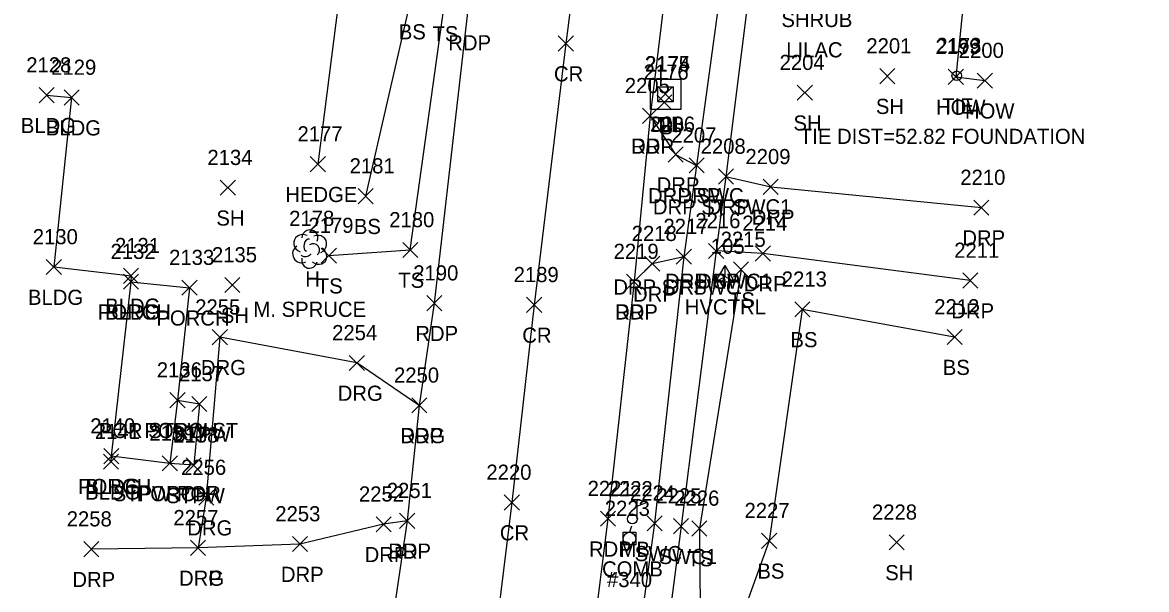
# Model space of a CAD drawing. Extents: x 1651305 to 1654558, y 539481 to 548441.
# Drawn here: x 1654294.9 to 1654443.3, y 544140.4 to 544215.2 of the extents above; entities that cross this region are included whole.
import ezdxf

# ---------------------------------------------------------------- set-up
doc = ezdxf.new("R2010")
doc.units = 0
for name, color, linetype in [('C_A', 7, 'Continuous'), ('C_C', 7, 'Continuous'), ('C_I', 7, 'Continuous'), ('CBP', 7, 'Continuous'), ('CPSM', 7, 'Continuous'), ('D_A', 7, 'Continuous'), ('D_I', 7, 'Continuous'), ('D_TIC', 7, 'Continuous'), ('DS', 7, 'Continuous'), ('L_A', 7, 'Continuous'), ('L_C', 7, 'Continuous'), ('L_I', 7, 'Continuous'), ('L_TIC', 7, 'Continuous'), ('LAHR', 7, 'Continuous'), ('LBC', 7, 'Continuous'), ('LBF', 7, 'Continuous'), ('LELB', 7, 'Continuous'), ('LMB', 7, 'Continuous'), ('LTD', 7, 'Continuous'), ('P_A', 7, 'Continuous'), ('P_I', 7, 'Continuous'), ('P_TIC', 7, 'Continuous'), ('PET', 7, 'Continuous'), ('PRC', 7, 'Continuous'), ('R_A', 7, 'Continuous'), ('R_I', 7, 'Continuous'), ('R_TIC', 7, 'Continuous'), ('RDG', 7, 'Continuous'), ('RDP', 7, 'Continuous'), ('RSW', 7, 'Continuous'), ('U_A', 7, 'Continuous'), ('U_I', 7, 'Continuous'), ('UP', 7, 'Continuous')]:
    doc.layers.add(name, color=color, linetype=linetype)

msp = doc.modelspace()

# ---------------------------------------------------------------- linework, layer by layer
at = {"layer": 'CBP'}
for radius in [0.625, 0.0833]:
    msp.add_circle((1654418.22, 544208.21), radius, dxfattribs=at)
at = {"layer": 'CPSM'}
for p, q in [((1654386.39, 544180.99), (1654387.64, 544183.16)), ((1654388.89, 544180.99), (1654387.64, 544183.16)), ((1654387.64, 544181.71), (1654387.64, 544183.16)), ((1654386.39, 544180.99), (1654387.64, 544181.71)), ((1654386.39, 544180.99), (1654388.89, 544180.99)), ((1654387.64, 544181.71), (1654387.64, 544181.71)), ((1654387.64, 544181.71), (1654388.89, 544180.99))]:
    msp.add_line(p, q, dxfattribs=at)
at = {"layer": 'D_TIC'}
for points in [[(1654378.75, 544204.8), (1654380.75, 544206.8)], [(1654380.75, 544204.8), (1654378.75, 544206.8)], [(1654378.63, 544203.69), (1654380.63, 544205.69)], [(1654380.63, 544203.69), (1654378.63, 544205.69)]]:
    msp.add_lwpolyline(points, dxfattribs=at)
at = {"layer": 'DS'}
for p, q in [((1654377.79, 544207.76), (1654381.79, 544207.76)), ((1654377.79, 544203.76), (1654377.79, 544207.76)), ((1654381.79, 544207.76), (1654381.79, 544203.76)), ((1654378.79, 544204.76), (1654378.79, 544206.76)), ((1654378.79, 544206.76), (1654380.79, 544206.76)), ((1654380.79, 544206.76), (1654380.79, 544204.76)), ((1654380.79, 544204.76), (1654378.79, 544204.76)), ((1654379.79, 544205.76), (1654379.79, 544205.76)), ((1654379.79, 544205.76), (1654379.79, 544205.76)), ((1654381.79, 544203.76), (1654377.79, 544203.76))]:
    msp.add_line(p, q, dxfattribs=at)
at = {"layer": 'L_TIC'}
for points in [[(1654408.06, 544207.16), (1654410.06, 544209.16)], [(1654410.06, 544207.16), (1654408.06, 544209.16)], [(1654417.1, 544207.06), (1654419.1, 544209.06)], [(1654419.1, 544207.06), (1654417.1, 544209.06)], [(1654420.92, 544206.56), (1654422.92, 544208.56)], [(1654422.92, 544206.56), (1654420.92, 544208.56)], [(1654297.1, 544204.64), (1654299.1, 544206.64)], [(1654299.1, 544204.64), (1654297.1, 544206.64)], [(1654300.4, 544204.33), (1654302.4, 544206.33)], [(1654302.4, 544204.33), (1654300.4, 544206.33)], [(1654397.18, 544204.97), (1654399.18, 544206.97)], [(1654399.18, 544204.97), (1654397.18, 544206.97)], [(1654332.9, 544195.54), (1654334.9, 544197.54)], [(1654334.9, 544195.54), (1654332.9, 544197.54)], [(1654321.01, 544192.43), (1654323.01, 544194.43)], [(1654323.01, 544192.43), (1654321.01, 544194.43)], [(1654339.21, 544191.32), (1654341.21, 544193.32)], [(1654341.21, 544191.32), (1654339.21, 544193.32)], [(1654334.35, 544183.47), (1654336.35, 544185.47)], [(1654336.35, 544183.47), (1654334.35, 544185.47)], [(1654345.1, 544184.22), (1654347.1, 544186.22)], [(1654347.1, 544184.22), (1654345.1, 544186.22)], [(1654298.05, 544181.97), (1654300.05, 544183.97)], [(1654300.05, 544181.97), (1654298.05, 544183.97)], [(1654308.24, 544180.8), (1654310.24, 544182.8)], [(1654310.24, 544180.8), (1654308.24, 544182.8)], [(1654388.75, 544181.63), (1654390.75, 544183.63)], [(1654390.75, 544181.63), (1654388.75, 544183.63)], [(1654308.23, 544180.03), (1654310.23, 544182.03)], [(1654310.23, 544180.03), (1654308.23, 544182.03)], [(1654308.23, 544180.03), (1654310.23, 544182.03)], [(1654310.23, 544180.03), (1654308.23, 544182.03)], [(1654315.96, 544179.24), (1654317.96, 544181.24)], [(1654317.96, 544179.24), (1654315.96, 544181.24)], [(1654321.61, 544179.59), (1654323.61, 544181.59)], [(1654323.61, 544179.59), (1654321.61, 544181.59)], [(1654396.83, 544176.38), (1654398.83, 544178.38)], [(1654398.83, 544176.38), (1654396.83, 544178.38)], [(1654416.94, 544172.72), (1654418.94, 544174.72)], [(1654418.94, 544172.72), (1654416.94, 544174.72)], [(1654314.38, 544164.39), (1654316.38, 544166.39)], [(1654316.38, 544164.39), (1654314.38, 544166.39)], [(1654314.38, 544164.39), (1654316.38, 544166.39)], [(1654316.38, 544164.39), (1654314.38, 544166.39)], [(1654317.26, 544163.9), (1654319.26, 544165.9)], [(1654319.26, 544163.9), (1654317.26, 544165.9)], [(1654305.63, 544157), (1654307.63, 544159)], [(1654307.63, 544157), (1654305.63, 544159)], [(1654305.63, 544157), (1654307.63, 544159)], [(1654307.63, 544157), (1654305.63, 544159)], [(1654305.59, 544156.27), (1654307.59, 544158.27)], [(1654307.59, 544156.27), (1654305.59, 544158.27)], [(1654313.37, 544156.06), (1654315.37, 544158.06)], [(1654315.37, 544156.06), (1654313.37, 544158.06)], [(1654313.37, 544156.06), (1654315.37, 544158.06)], [(1654315.37, 544156.06), (1654313.37, 544158.06)], [(1654316.51, 544155.8), (1654318.51, 544157.8)], [(1654318.51, 544155.8), (1654316.51, 544157.8)], [(1654383.25, 544147.47), (1654385.25, 544149.47)], [(1654385.25, 544147.47), (1654383.25, 544149.47)], [(1654392.47, 544145.84), (1654394.47, 544147.84)], [(1654394.47, 544145.84), (1654392.47, 544147.84)], [(1654409.29, 544145.63), (1654411.29, 544147.63)], [(1654411.29, 544145.63), (1654409.29, 544147.63)]]:
    msp.add_lwpolyline(points, dxfattribs=at)
at = {"layer": 'LAHR'}
msp.add_lwpolyline([(1654343.12, 544269.12), (1654333.9, 544196.54)], dxfattribs=at)
at = {"layer": 'LBC'}
for points in [[(1654425.69, 544242.58), (1654421.57, 544242.91), (1654420.13, 544229.87), (1654419.58, 544222.88), (1654418.1, 544208.06), (1654421.92, 544207.56)], [(1654298.1, 544205.64), (1654301.4, 544205.33), (1654299.05, 544182.97), (1654309.24, 544181.8), (1654309.23, 544181.03), (1654306.63, 544158), (1654306.59, 544157.27)]]:
    msp.add_lwpolyline(points, dxfattribs=at)
at = {"layer": 'LBF'}
for points in [[(1654309.23, 544181.03), (1654316.96, 544180.24), (1654315.38, 544165.39), (1654314.37, 544157.06), (1654306.63, 544158)], [(1654315.38, 544165.39), (1654318.26, 544164.9), (1654317.51, 544156.8), (1654314.37, 544157.06)]]:
    msp.add_lwpolyline(points, dxfattribs=at)
at = {"layer": 'LELB'}
for points in [[(1654340.21, 544192.32), (1654346.14, 544218.01), (1654348.85, 544254.55)], [(1654335.35, 544184.47), (1654346.1, 544185.22), (1654350.62, 544217.75), (1654352.84, 544250.3)], [(1654389.75, 544182.63), (1654384.25, 544148.47), (1654384.51, 544121.92), (1654406.01, 544119.98)], [(1654417.94, 544173.72), (1654397.83, 544177.38), (1654393.47, 544146.84), (1654384.51, 544121.92), (1654381.65, 544104.55), (1654379.35, 544091.34), (1654377.04, 544088.64), (1654375.52, 544071.52)]]:
    msp.add_lwpolyline(points, dxfattribs=at)
at = {"layer": 'LMB'}
for p, q in [((1654376.06, 544152.32), (1654377.35, 544151.94)), ((1654376.06, 544149.73), (1654376.06, 544152.32)), ((1654376.06, 544151.42), (1654377.34, 544151.93)), ((1654375.41, 544149.72), (1654375.41, 544149.72))]:
    msp.add_line(p, q, dxfattribs=at)
msp.add_circle((1654375.41, 544149.72), 0.656, dxfattribs=at)
at = {"layer": 'LTD'}
msp.add_line((1654332.8, 544185.39), (1654332.8, 544185.39), dxfattribs=at)
msp.add_line((1654332.8, 544185.39), (1654332.8, 544185.39), dxfattribs=at)
msp.add_arc((1654332.85, 544186.82), 1.05, 335.5272, 180.9563, dxfattribs=at)
for centre, major_axis, ratio, start_param, end_param in [((1654332.01, 544186.05), (1.21, -0.51), 0.895232, 1.570796, 4.712389), ((1654333.84, 544185.97), (-1.14, -0.48), 0.949671, 1.570796, 4.712389), ((1654331.72, 544184.68), (0.58, -1.04), 0.959034, 3.141593, 6.283185), ((1654332.59, 544185.85), (-0.208, -0.792), 0.645439, 3.141593, 6.283185), ((1654333.3, 544185.22), (-0.5, 0.667), 0.989748, 3.141593, 6.283185), ((1654333.8, 544184.55), (-1.09, 0.79), 0.841452, 1.570796, 4.712389), ((1654332.8, 544183.89), (0.26, 1.06), 0.942809, 1.570796, 4.712389), ((1654332.34, 544184.64), (-0.625, -0.083), 0.423636, 0, 3.141593)]:
    msp.add_ellipse(centre, major_axis=major_axis, ratio=ratio, start_param=start_param, end_param=end_param, dxfattribs=at)
at = {"layer": 'P_TIC'}
for points in [[(1654365.63, 544211.46), (1654367.63, 544213.46)], [(1654367.63, 544211.46), (1654365.63, 544213.46)], [(1654376.75, 544201.91), (1654378.75, 544203.91)], [(1654378.75, 544201.91), (1654376.75, 544203.91)], [(1654374.63, 544180.04), (1654376.63, 544182.04)], [(1654376.63, 544180.04), (1654374.63, 544182.04)], [(1654348.27, 544177.19), (1654350.27, 544179.19)], [(1654350.27, 544177.19), (1654348.27, 544179.19)], [(1654361.44, 544176.97), (1654363.44, 544178.97)], [(1654363.44, 544176.97), (1654361.44, 544178.97)], [(1654346.29, 544163.71), (1654348.29, 544165.71)], [(1654348.29, 544163.71), (1654346.29, 544165.71)], [(1654358.49, 544150.89), (1654360.49, 544152.89)], [(1654360.49, 544150.89), (1654358.49, 544152.89)], [(1654344.69, 544148.48), (1654346.69, 544150.48)], [(1654346.69, 544148.48), (1654344.69, 544150.48)], [(1654371.19, 544148.75), (1654373.19, 544150.75)], [(1654373.19, 544148.75), (1654371.19, 544150.75)]]:
    msp.add_lwpolyline(points, dxfattribs=at)
at = {"layer": 'PET'}
for points in [[(1654345.04, 544588.36), (1654350.59, 544607.19), (1654356.58, 544624.31), (1654366.69, 544597.7), (1654378.7, 544565.63), (1654388.8, 544536.02), (1654394.39, 544506.43), (1654399.12, 544481.01), (1654401.13, 544462.89), (1654401.53, 544436.35), (1654401.83, 544421.31), (1654397.37, 544359.7), (1654394.39, 544336.59), (1654391.4, 544308.96), (1654388.94, 544290.74), (1654386.84, 544274.06), (1654380.97, 544229.45), (1654377.75, 544202.91), (1654375.63, 544181.04), (1654372.19, 544149.75), (1654366.61, 544105.72), (1654362.8, 544072.79)], [(1654345.04, 544588.36), (1654352.84, 544566.03), (1654357.71, 544551.64), (1654360.67, 544540.21), (1654367.97, 544503.91), (1654371.19, 544473.22), (1654373.31, 544432.69), (1654372.37, 544396.63), (1654369.95, 544367.4), (1654366.85, 544341.54), (1654364.49, 544322.02), (1654359.18, 544276.5), (1654356.39, 544249.38), (1654353.63, 544216.56), (1654349.27, 544178.19), (1654347.29, 544164.71), (1654345.69, 544149.48), (1654340.92, 544117.48), (1654336.05, 544077.13)]]:
    msp.add_lwpolyline(points, dxfattribs=at)
at = {"layer": 'PRC'}
msp.add_lwpolyline([(1654350.59, 544607.19), (1654355.93, 544592.7), (1654363.68, 544570.63), (1654372.22, 544542.27), (1654380.24, 544505.39), (1654384.95, 544473.92), (1654386.82, 544433.75), (1654385.71, 544395.52), (1654383.86, 544366), (1654380.92, 544339.65), (1654378, 544311.09), (1654373.89, 544274.84), (1654369.01, 544231.01), (1654366.63, 544212.46), (1654362.44, 544177.97), (1654359.49, 544151.89), (1654354.07, 544107.93), (1654348.42, 544063.01)], dxfattribs=at)
at = {"layer": 'R_TIC'}
for points in [[(1654376.75, 544201.91), (1654378.75, 544203.91)], [(1654378.75, 544201.91), (1654376.75, 544203.91)], [(1654380.12, 544196.82), (1654382.12, 544198.82)], [(1654382.12, 544196.82), (1654380.12, 544198.82)], [(1654382.89, 544195.38), (1654384.89, 544197.38)], [(1654384.89, 544195.38), (1654382.89, 544197.38)], [(1654382.89, 544195.38), (1654384.89, 544197.38)], [(1654384.89, 544195.38), (1654382.89, 544197.38)], [(1654386.76, 544193.91), (1654388.76, 544195.91)], [(1654388.76, 544193.91), (1654386.76, 544195.91)], [(1654386.76, 544193.91), (1654388.76, 544195.91)], [(1654388.76, 544193.91), (1654386.76, 544195.91)], [(1654392.67, 544192.54), (1654394.67, 544194.54)], [(1654394.67, 544192.54), (1654392.67, 544194.54)], [(1654420.47, 544189.81), (1654422.47, 544191.81)], [(1654422.47, 544189.81), (1654420.47, 544191.81)], [(1654385.47, 544184.09), (1654387.47, 544186.09)], [(1654387.47, 544184.09), (1654385.47, 544186.09)], [(1654385.47, 544184.09), (1654387.47, 544186.09)], [(1654387.47, 544184.09), (1654385.47, 544186.09)], [(1654391.62, 544183.76), (1654393.62, 544185.76)], [(1654393.62, 544183.76), (1654391.62, 544185.76)], [(1654377.02, 544182.4), (1654379.02, 544184.4)], [(1654379.02, 544182.4), (1654377.02, 544184.4)], [(1654381.2, 544183.33), (1654383.2, 544185.33)], [(1654383.2, 544183.33), (1654381.2, 544185.33)], [(1654381.2, 544183.33), (1654383.2, 544185.33)], [(1654383.2, 544183.33), (1654381.2, 544185.33)], [(1654374.63, 544180.04), (1654376.63, 544182.04)], [(1654376.63, 544180.04), (1654374.63, 544182.04)], [(1654419.01, 544180.18), (1654421.01, 544182.18)], [(1654421.01, 544180.18), (1654419.01, 544182.18)], [(1654319.97, 544172.7), (1654321.97, 544174.7)], [(1654321.97, 544172.7), (1654319.97, 544174.7)], [(1654338.04, 544169.31), (1654340.04, 544171.31)], [(1654340.04, 544169.31), (1654338.04, 544171.31)], [(1654346.29, 544163.71), (1654348.29, 544165.71)], [(1654348.29, 544163.71), (1654346.29, 544165.71)], [(1654318.17, 544151.54), (1654320.17, 544153.54)], [(1654320.17, 544151.54), (1654318.17, 544153.54)], [(1654341.58, 544148.02), (1654343.58, 544150.02)], [(1654343.58, 544148.02), (1654341.58, 544150.02)], [(1654344.69, 544148.48), (1654346.69, 544150.48)], [(1654346.69, 544148.48), (1654344.69, 544150.48)], [(1654377.35, 544148.15), (1654379.35, 544150.15)], [(1654379.35, 544148.15), (1654377.35, 544150.15)], [(1654380.83, 544147.77), (1654382.83, 544149.77)], [(1654382.83, 544147.77), (1654380.83, 544149.77)], [(1654317.09, 544144.9), (1654319.09, 544146.9)], [(1654319.09, 544144.9), (1654317.09, 544146.9)], [(1654317.09, 544144.9), (1654319.09, 544146.9)], [(1654319.09, 544144.9), (1654317.09, 544146.9)], [(1654330.54, 544145.41), (1654332.54, 544147.41)], [(1654332.54, 544145.41), (1654330.54, 544147.41)], [(1654303.01, 544144.73), (1654305.01, 544146.73)], [(1654305.01, 544144.73), (1654303.01, 544146.73)]]:
    msp.add_lwpolyline(points, dxfattribs=at)
at = {"layer": 'RDG'}
msp.add_lwpolyline([(1654347.29, 544164.71), (1654339.04, 544170.31), (1654320.97, 544173.7), (1654319.17, 544152.54), (1654318.09, 544145.9)], dxfattribs=at)
at = {"layer": 'RDP'}
for points in [[(1654377.75, 544202.91), (1654381.12, 544197.82), (1654383.89, 544196.38)], [(1654387.76, 544194.91), (1654393.67, 544193.54), (1654421.47, 544190.81)], [(1654382.2, 544184.33), (1654378.02, 544183.4), (1654375.63, 544181.04)], [(1654420.01, 544181.18), (1654392.62, 544184.76), (1654386.47, 544185.09)], [(1654345.69, 544149.48), (1654342.58, 544149.02), (1654331.54, 544146.41), (1654318.09, 544145.9), (1654304.01, 544145.73)]]:
    msp.add_lwpolyline(points, dxfattribs=at)
at = {"layer": 'RSW'}
for points in [[(1654407.4, 544661.78), (1654407.29, 544658.87), (1654407.96, 544657.88), (1654443.27, 544654.59), (1654438.81, 544619.89), (1654433.56, 544580.17), (1654430.14, 544553.99), (1654428.03, 544537.28), (1654424.83, 544512.84), (1654419.77, 544473.61), (1654412.66, 544419.66), (1654404.12, 544354.77), (1654402.1, 544339.77), (1654395.49, 544286.06), (1654394.01, 544276.12), (1654388.39, 544229.58), (1654383.89, 544196.38), (1654382.2, 544184.33), (1654378.35, 544149.15), (1654372.36, 544105.49), (1654368.55, 544072.05)], [(1654411.79, 544225.19), (1654397.44, 544226.9), (1654391.8, 544227.25), (1654387.76, 544194.91), (1654386.47, 544185.09), (1654381.83, 544148.77), (1654376.18, 544105.12), (1654374.34, 544091.89), (1654373.97, 544088.88), (1654371.75, 544071.94)]]:
    msp.add_lwpolyline(points, dxfattribs=at)
at = {"layer": 'UP'}
for p, q in [((1654375.28, 544148.79), (1654375.03, 544147.96)), ((1654374.19, 544146.29), (1654374.19, 544147.96)), ((1654374.19, 544147.96), (1654375.86, 544147.96)), ((1654375.03, 544147.13), (1654375.03, 544147.13)), ((1654375.86, 544147.96), (1654375.86, 544146.29)), ((1654375.86, 544146.29), (1654374.19, 544146.29)), ((1654374.78, 544145.46), (1654375.03, 544146.29))]:
    msp.add_line(p, q, dxfattribs=at)
msp.add_circle((1654375.03, 544147.13), 0.833, dxfattribs=at)

# ---------------------------------------------------------------- texts
at = {"layer": 'C_A'}
for s, p in [('TIE', (1654416.3, 544203.21)), ('HVCTRL', (1654382.33, 544176.71))]:
    msp.add_text(s, height=2, dxfattribs=at).set_placement(p)
at = {"layer": 'C_C'}
msp.add_text('TIE DIST=52.82 FOUNDATION', height=2, dxfattribs=at).set_placement((1654397.52, 544199.21))
at = {"layer": 'C_I'}
for s, p in [('2173', (1654415.53, 544211.21)), ('105', (1654385.77, 544184.71))]:
    msp.add_text(s, height=2, dxfattribs=at).set_placement(p)
at = {"layer": 'D_A'}
for s, p in [('DIB', (1654377.85, 544200.8)), ('DI', (1654378.85, 544200.76)), ('P', (1654379.01, 544199.69))]:
    msp.add_text(s, height=2, dxfattribs=at).set_placement(p)
at = {"layer": 'D_I'}
for s, p in [('2175', (1654377.06, 544208.8)), ('2174', (1654377.1, 544208.76)), ('2176', (1654376.89, 544207.69))]:
    msp.add_text(s, height=2, dxfattribs=at).set_placement(p)
at = {"layer": 'L_A'}
for s, p in [('SHRUB', (1654395.08, 544214.63)), ('BS', (1654344.58, 544213.01)), ('TS', (1654349.03, 544212.75)), ('SH', (1654407.55, 544203.16)), ('HOW', (1654415.49, 544203.06)), ('HOW', (1654419.3, 544202.56)), ('BLDG', (1654294.69, 544200.64)), ('BLDG', (1654297.99, 544200.33)), ('SH', (1654396.67, 544200.97)), ('HEDGE', (1654329.6, 544191.54)), ('SH', (1654320.5, 544188.43)), ('BS', (1654338.65, 544187.32)), ('H', (1654332.23, 544180.39)), ('TS', (1654333.76, 544179.47)), ('TS', (1654344.51, 544180.22)), ('BLDG', (1654295.64, 544177.97)), ('TS', (1654388.16, 544177.63)), ('PORCH', (1654304.85, 544176.03)), ('BLDG', (1654305.82, 544176.03)), ('BLDG', (1654305.83, 544176.8)), ('PORCH', (1654312.59, 544175.24)), ('SH', (1654321.1, 544175.59)), ('BS', (1654396.27, 544172.38)), ('BS', (1654416.38, 544168.72)), ('POR STPW ST', (1654304.97, 544160.39)), ('PORCH', (1654311.01, 544160.39)), ('STPW', (1654314.66, 544159.9)), ('PORCH', (1654302.25, 544153)), ('BLDG', (1654303.18, 544152.27)), ('BLDG', (1654303.22, 544153)), ('STPW POR', (1654306.82, 544152.06)), ('PORCH', (1654309.99, 544152.06)), ('STPW', (1654313.9, 544151.8)), ('MB', (1654373.71, 544144.72)), ('TS', (1654382.66, 544143.47)), ('BS', (1654391.91, 544141.84)), ('SH', (1654408.78, 544141.63))]:
    msp.add_text(s, height=2, dxfattribs=at).set_placement(p)
at = {"layer": 'L_C'}
for s, p in [('LILAC', (1654395.72, 544210.63)), ('M. SPRUCE', (1654325.4, 544176.39)), ('#340', (1654372.06, 544140.72))]:
    msp.add_text(s, height=2, dxfattribs=at).set_placement(p)
at = {"layer": 'L_I'}
for s, p in [('2201', (1654406.29, 544211.16)), ('2199', (1654415.4, 544211.06)), ('2200', (1654418.49, 544210.56)), ('2128', (1654295.41, 544208.64)), ('2204', (1654394.84, 544208.97)), ('2129', (1654298.7, 544208.33)), ('2177', (1654331.21, 544199.54)), ('2134', (1654319.32, 544196.43)), ('2181', (1654338.09, 544195.32)), ('2178', (1654330.11, 544188.39)), ('2180', (1654343.32, 544188.22)), ('2179', (1654332.65, 544187.47)), ('2130', (1654296.27, 544185.97)), ('2215', (1654387.06, 544185.63)), ('2132', (1654306.54, 544184.03)), ('2132', (1654306.54, 544184.03)), ('2131', (1654307.12, 544184.8)), ('2135', (1654319.92, 544183.59)), ('2133', (1654314.27, 544183.24)), ('2213', (1654395.13, 544180.38)), ('2212', (1654415.25, 544176.72)), ('2136', (1654312.64, 544168.39)), ('2136', (1654312.64, 544168.39)), ('2137', (1654315.57, 544167.9)), ('2140', (1654303.85, 544161)), ('2140', (1654303.85, 544161)), ('2141', (1654304.46, 544160.27)), ('2139', (1654311.67, 544160.06)), ('2139', (1654311.67, 544160.06)), ('2138', (1654314.81, 544159.8)), ('2222', (1654372.15, 544152.72)), ('2226', (1654380.94, 544151.47)), ('2227', (1654390.21, 544149.84)), ('2228', (1654407.03, 544149.63))]:
    msp.add_text(s, height=2, dxfattribs=at).set_placement(p)
at = {"layer": 'P_A'}
for s, p in [('RDP', (1654351.11, 544211.56)), ('CR', (1654365.06, 544207.46)), ('RDP', (1654375.24, 544197.91)), ('RDP', (1654373.12, 544176.04)), ('RDP', (1654346.76, 544173.19)), ('CR', (1654360.88, 544172.97)), ('RDP', (1654344.78, 544159.71)), ('CR', (1654357.92, 544146.89)), ('RDP', (1654343.18, 544144.48)), ('RDP', (1654369.68, 544144.75))]:
    msp.add_text(s, height=2, dxfattribs=at).set_placement(p)
at = {"layer": 'P_I'}
for s, p in [('2205', (1654374.41, 544205.91)), ('2219', (1654372.93, 544184.04)), ('2190', (1654346.49, 544181.19)), ('2189', (1654359.74, 544180.97)), ('2250', (1654343.95, 544167.71)), ('2220', (1654356.14, 544154.89)), ('2251', (1654343, 544152.48)), ('2221', (1654369.5, 544152.75))]:
    msp.add_text(s, height=2, dxfattribs=at).set_placement(p)
at = {"layer": 'R_A'}
for s, p in [('DRP', (1654375.24, 544197.91)), ('DRP', (1654378.61, 544192.82)), ('DRP SWC', (1654377.47, 544191.38)), ('DRP', (1654381.38, 544191.38)), ('DRP ST SWC1', (1654378.12, 544189.91)), ('DRP', (1654385.25, 544189.91)), ('DRP', (1654391.16, 544188.54)), ('DRP', (1654418.96, 544185.81)), ('DRP ST SWC', (1654372.89, 544179.33)), ('DRP', (1654379.69, 544179.33)), ('DRP SWC1', (1654379.73, 544180.09)), ('DRP', (1654383.96, 544180.09)), ('DRP', (1654390.11, 544179.76)), ('DRP', (1654375.5, 544178.4)), ('DRP', (1654373.12, 544176.04)), ('DRP', (1654417.5, 544176.18)), ('DRG', (1654318.46, 544168.7)), ('DRG', (1654336.52, 544165.31)), ('DRG', (1654344.78, 544159.71)), ('DRG', (1654316.66, 544147.54)), ('DRP', (1654340.07, 544144.02)), ('DRP', (1654343.18, 544144.48)), ('SWC', (1654375.71, 544144.15)), ('SWC1', (1654378.87, 544143.77)), ('DRP', (1654301.5, 544140.73)), ('DRG', (1654315.58, 544140.9)), ('DRP', (1654315.58, 544140.9)), ('DRP', (1654329.02, 544141.41))]:
    msp.add_text(s, height=2, dxfattribs=at).set_placement(p)
at = {"layer": 'R_I'}
for s, p in [('2205', (1654374.41, 544205.91)), ('2206', (1654377.73, 544200.82)), ('2207', (1654380.55, 544199.38)), ('2207', (1654380.55, 544199.38)), ('2208', (1654384.42, 544197.91)), ('2208', (1654384.42, 544197.91)), ('2209', (1654390.33, 544196.54)), ('2210', (1654418.69, 544193.81)), ('2216', (1654383.72, 544188.09)), ('2216', (1654383.72, 544188.09)), ('2218', (1654375.32, 544186.4)), ('2217', (1654379.51, 544187.33)), ('2217', (1654379.51, 544187.33)), ('2214', (1654389.92, 544187.76)), ('2219', (1654372.93, 544184.04)), ('2211', (1654417.89, 544184.18)), ('2255', (1654317.71, 544176.7)), ('2254', (1654335.78, 544173.31)), ('2250', (1654343.95, 544167.71)), ('2256', (1654315.85, 544155.54)), ('2251', (1654343, 544152.48)), ('2252', (1654339.32, 544152.02)), ('2224', (1654375.09, 544152.15)), ('2225', (1654378.57, 544151.77)), ('2253', (1654328.28, 544149.41)), ('2258', (1654300.75, 544148.73)), ('2257', (1654314.83, 544148.9)), ('2257', (1654314.83, 544148.9))]:
    msp.add_text(s, height=2, dxfattribs=at).set_placement(p)
at = {"layer": 'U_A'}
msp.add_text('COMB', height=2, dxfattribs=at).set_placement((1654371.41, 544142.13))
at = {"layer": 'U_I'}
msp.add_text('2223', height=2, dxfattribs=at).set_placement((1654371.77, 544150.13))

doc.saveas('drawing.dxf')
